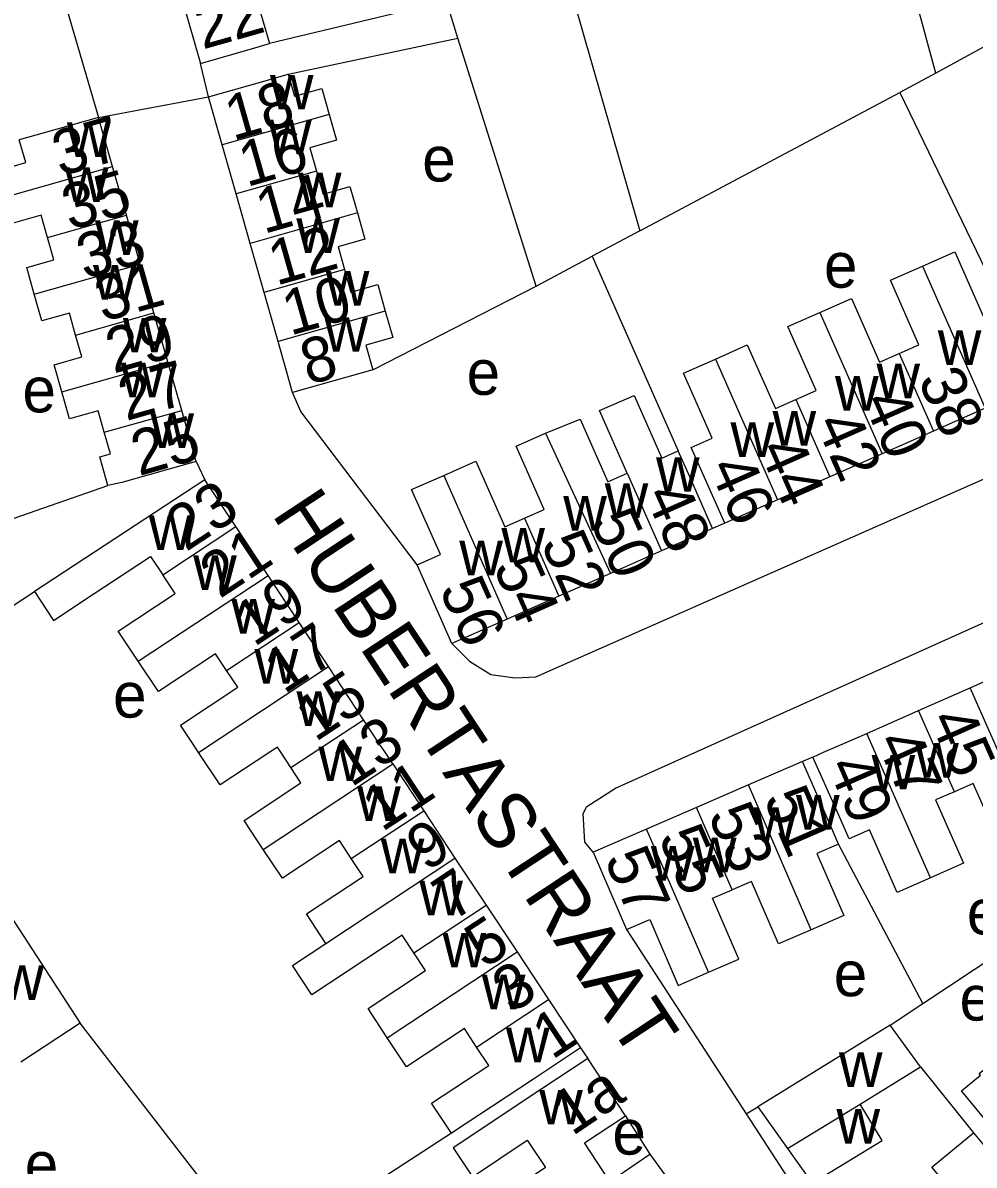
# Model space of a CAD drawing. Extents: x 159261 to 160849, y 382514 to 384534.
# Drawn here: x 160270.2 to 160354.6, y 383463.4 to 383564.7 of the extents above; entities that cross this region are included whole.
import ezdxf

# ---------------------------------------------------------------- set-up
doc = ezdxf.new("R2010")
doc.units = 0
for name, color, linetype in [('BLT_Basislijn', 7, 'Continuous'), ('BLT_Bebouwing', 7, 'Continuous'), ('BLT_Centroide', 7, 'Continuous'), ('BLT_Huisnummer', 7, 'Continuous'), ('BLT_Huisnummer_ tussenligend', 7, 'Continuous'), ('BLT_Huisnummer_reeks', 7, 'Continuous'), ('BLT_Onderverdeling_panden', 7, 'Continuous'), ('BLT_Straatnaam', 7, 'Continuous'), ('BLT_Vlakafsluiter', 7, 'Continuous')]:
    doc.layers.add(name, color=color, linetype=linetype)

msp = doc.modelspace()

# ---------------------------------------------------------------- linework, layer by layer
at = {"layer": 'BLT_Basislijn'}
for p, q in [((160315.03, 383580.9), (160324.95, 383546.27)), ((160373.11, 383572.25), (160351.21, 383560.24)), ((160273.28, 383568.79), (160276.93, 383556.33)), ((160293.77, 383560.15), (160308.8, 383563.35)), ((160315.77, 383541.34), (160308.8, 383563.35)), ((160286.7, 383558.14), (160285.99, 383561.11)), ((160351.21, 383560.24), (160348.01, 383558.54)), ((160324.95, 383546.27), (160348.01, 383558.54)), ((160348.01, 383558.54), (160357.2, 383539.49)), ((160324.95, 383546.27), (160320.72, 383544.01)), ((160315.77, 383541.34), (160320.72, 383544.01)), ((160320.72, 383544.01), (160328.36, 383526.74)), ((160301.28, 383533.94), (160315.77, 383541.34)), ((160285.59, 383525.8), (160286.37, 383524.16)), ((160268.86, 383520.57), (160277.76, 383523.68)), ((160332.49, 383520.33), (160331.39, 383519.86)), ((160266.28, 383511.01), (160271.25, 383514.26)), ((160340.31, 383499.58), (160339.4, 383499.18)), ((160350.07, 383477.72), (160375.85, 383494.83)), ((160350.07, 383477.72), (160342.58, 383491.85)), ((160323.78, 383484.27), (160334.4, 383467.92)), ((160347.17, 383475.8), (160350.07, 383477.72)), ((160287.38, 383460.38), (160275.29, 383475.98)), ((160319.69, 383473.77), (160320.33, 383472.82)), ((160349.86, 383472.08), (160354.56, 383466.25)), ((160323.68, 383467.76), (160325.85, 383464.35)), ((160334.4, 383467.92), (160335.42, 383468.56)), ((160334.4, 383467.92), (160347.36, 383447.97)), ((160308.24, 383466.2), (160291.06, 383455.07)), ((160322.29, 383461.92), (160325.85, 383464.35)), ((160325.85, 383464.35), (160327.16, 383462.51))]:
    msp.add_line(p, q, dxfattribs=at)
for points in [[(160308.29, 383509.66), (160309.84, 383508.09), (160311.74, 383506.91), (160313.89, 383506.61), (160315.74, 383506.7), (160377.81, 383534.11), (160390.63, 383541.51), (160406.21, 383552.19), (160447.07, 383583.47), (160450.73, 383593.39)], [(160351.21, 383560.24), (160346.25, 383578.54), (160343.07, 383588.58)], [(160320.81, 383491.14), (160320.08, 383492.03), (160319.93, 383494.56), (160320.25, 383495.2), (160322.79, 383496.82), (160377.81, 383521.53), (160402.11, 383534.27), (160431.08, 383555.98), (160454.87, 383574.92), (160465.53, 383577.42)], [(160308.8, 383563.35), (160307.81, 383566.63), (160292.1, 383562.87)], [(160305.21, 383516.64), (160294.89, 383530.22), (160294.14, 383531.91)]]:
    msp.add_lwpolyline(points, dxfattribs=at)
at = {"layer": 'BLT_Bebouwing'}
for p, q in [((160289.44, 383572.14), (160292.1, 383562.87)), ((160283.32, 383570.38), (160285.99, 383561.11)), ((160287.9, 383553.9), (160286.7, 383558.14)), ((160278.17, 383551.96), (160276.93, 383556.33)), ((160289.14, 383549.54), (160287.9, 383553.9)), ((160279.4, 383547.64), (160278.17, 383551.96)), ((160290.39, 383545.15), (160289.14, 383549.54)), ((160280.63, 383543.3), (160279.4, 383547.64)), ((160291.62, 383540.8), (160290.39, 383545.15)), ((160281.85, 383538.99), (160280.63, 383543.3)), ((160292.86, 383536.45), (160291.62, 383540.8)), ((160283.08, 383534.64), (160281.85, 383538.99)), ((160294.14, 383531.91), (160292.86, 383536.45)), ((160284.31, 383530.33), (160283.08, 383534.64)), ((160355.6, 383530.52), (160351, 383528.49)), ((160285.59, 383525.8), (160284.31, 383530.33)), ((160351, 383528.49), (160346.45, 383526.48)), ((160346.45, 383526.48), (160341.81, 383524.44)), ((160341.81, 383524.44), (160337.17, 383522.39)), ((160286.37, 383524.16), (160271.25, 383514.26)), ((160289.11, 383520.02), (160286.37, 383524.16)), ((160337.17, 383522.39), (160332.49, 383520.33)), ((160291.97, 383515.69), (160289.11, 383520.02)), ((160331.39, 383519.86), (160326.88, 383517.86)), ((160326.88, 383517.86), (160322.34, 383515.86)), ((160308.29, 383509.66), (160305.21, 383516.64)), ((160294.74, 383511.51), (160291.97, 383515.69)), ((160322.34, 383515.86), (160317.77, 383513.85)), ((160317.77, 383513.85), (160313.18, 383511.82)), ((160297.32, 383507.6), (160294.74, 383511.51)), ((160313.18, 383511.82), (160308.29, 383509.66)), ((160300.44, 383502.89), (160297.32, 383507.6)), ((160354.25, 383505.73), (160358.91, 383507.78)), ((160349.68, 383503.71), (160354.25, 383505.73)), ((160345.08, 383501.68), (160349.68, 383503.71)), ((160339.4, 383499.18), (160334.59, 383497.1)), ((160303.03, 383498.97), (160305.78, 383494.82)), ((160334.59, 383497.1), (160329.98, 383495.1)), ((160329.98, 383495.1), (160325.56, 383493.19)), ((160305.78, 383494.82), (160308.55, 383490.61)), ((160325.56, 383493.19), (160320.81, 383491.14)), ((160320.81, 383491.14), (160323.78, 383484.27)), ((160308.55, 383490.61), (160311.32, 383486.43)), ((160311.32, 383486.43), (160314.06, 383482.29)), ((160269.1, 383485.53), (160275.29, 383475.98)), ((160314.06, 383482.29), (160316.85, 383478.07)), ((160316.85, 383478.07), (160319.69, 383473.77)), ((160275.29, 383475.98), (160270.03, 383472.52)), ((160347.17, 383475.8), (160335.42, 383468.56)), ((160349.86, 383472.08), (160347.17, 383475.8)), ((160323.68, 383467.76), (160320.33, 383472.82))]:
    msp.add_line(p, q, dxfattribs=at)
for points in [[(160285.99, 383561.11), (160290.8, 383562.49), (160292.1, 383562.87)], [(160286.7, 383558.14), (160291.51, 383559.51), (160293.77, 383560.15)], [(160293.77, 383560.15), (160294.32, 383558.21), (160296.73, 383558.89), (160297.39, 383556.59)], [(160276.93, 383556.33), (160272.12, 383554.97), (160269.9, 383554.34)], [(160297.39, 383556.59), (160298.04, 383554.3), (160295.68, 383553.62), (160296.26, 383551.56)], [(160268.7, 383549.28), (160268.03, 383551.62), (160270.47, 383552.31), (160269.9, 383554.34)], [(160296.26, 383551.56), (160296.85, 383549.51), (160299.24, 383550.19), (160299.91, 383547.85)], [(160272.41, 383545.66), (160271.85, 383547.64), (160269.36, 383546.93), (160268.7, 383549.28)], [(160299.91, 383547.85), (160300.57, 383545.51), (160298.2, 383544.84), (160298.76, 383542.83)], [(160271.23, 383540.64), (160270.56, 383543), (160272.97, 383543.68), (160272.41, 383545.66)], [(160350.04, 383543.14), (160352.9, 383544.4), (160355.41, 383538.7), (160357.2, 383539.49)], [(160298.76, 383542.83), (160299.33, 383540.82), (160301.71, 383541.5), (160302.37, 383539.15)], [(160347.97, 383535.37), (160349.71, 383536.14), (160347.18, 383541.88), (160350.04, 383543.14)], [(160274.9, 383537.02), (160274.35, 383538.97), (160271.9, 383538.27), (160271.23, 383540.64)], [(160340.91, 383539.02), (160343.73, 383540.27), (160346.23, 383534.6), (160347.97, 383535.37)], [(160302.37, 383539.15), (160303.04, 383536.81), (160300.65, 383536.13), (160301.28, 383533.94)], [(160338.79, 383531.29), (160340.61, 383532.09), (160338.1, 383537.78), (160340.91, 383539.02)], [(160273.69, 383531.98), (160273.01, 383534.37), (160275.45, 383535.07), (160274.9, 383537.02)], [(160331.66, 383534.89), (160334.49, 383536.14), (160336.98, 383530.49), (160338.79, 383531.29)], [(160332.49, 383520.33), (160330.47, 383524.9), (160329.52, 383527.05), (160331.38, 383527.87), (160328.83, 383533.64), (160331.66, 383534.89)], [(160301.28, 383533.94), (160298.95, 383533.28), (160294.14, 383531.91)], [(160277.44, 383528.39), (160276.9, 383530.3), (160274.37, 383529.58), (160273.69, 383531.98)], [(160323.84, 383524.76), (160321.39, 383530.31), (160324.44, 383531.66), (160326.9, 383526.09), (160328.36, 383526.74)], [(160316.6, 383528.31), (160319.66, 383529.56), (160322.12, 383524), (160323.84, 383524.76)], [(160277.76, 383523.68), (160277.04, 383526.2), (160277.99, 383526.47), (160277.44, 383528.39)], [(160314.72, 383520.77), (160316.46, 383521.54), (160313.99, 383527.16), (160316.6, 383528.31)], [(160331.39, 383519.86), (160329.38, 383524.43), (160328.36, 383526.74)], [(160285.59, 383525.8), (160279.01, 383523.93), (160277.76, 383523.68)], [(160307.56, 383524.56), (160310.4, 383525.82), (160312.97, 383520), (160314.72, 383520.77)], [(160305.21, 383516.64), (160307.26, 383517.54), (160304.71, 383523.31), (160307.56, 383524.56)], [(160271.25, 383514.26), (160272.95, 383511.69), (160276.47, 383514.02), (160281.54, 383517.38), (160282.63, 383515.73)], [(160280.46, 383508.07), (160278.68, 383510.75), (160283.72, 383514.09), (160282.63, 383515.73)], [(160288.3, 383507.25), (160287.32, 383508.74), (160282.24, 383505.38), (160280.46, 383508.07)], [(160285.81, 383499.99), (160285.32, 383500.73), (160284.21, 383502.4), (160289.28, 383505.77), (160288.3, 383507.25)], [(160303.03, 383498.97), (160302.35, 383500), (160301.87, 383500.73), (160300.44, 383502.89)], [(160340.31, 383499.58), (160341.26, 383500), (160342.9, 383500.73), (160345.08, 383501.68)], [(160294, 383498.64), (160293.1, 383500), (160292.8, 383500.45), (160292.12, 383500), (160287.72, 383497.1), (160285.81, 383499.99)], [(160342.58, 383491.85), (160341.39, 383494.6), (160339.4, 383499.18)], [(160350.73, 383488.86), (160347.79, 383487.57), (160345.34, 383493.11), (160343.52, 383492.31), (160342.33, 383495.01), (160340.31, 383499.58)], [(160291.55, 383491.39), (160289.85, 383493.96), (160294.89, 383497.29), (160294, 383498.64)], [(160359.87, 383492.97), (160356.97, 383491.69), (160354.52, 383497.24), (160352.86, 383496.5)], [(160352.86, 383496.5), (160351.19, 383495.77), (160353.67, 383490.16), (160350.73, 383488.86)], [(160299.35, 383490.57), (160298.31, 383492.16), (160293.25, 383488.82), (160291.55, 383491.39)], [(160342.58, 383491.85), (160340.66, 383491.02), (160343.04, 383485.52), (160340.15, 383484.26)], [(160297.1, 383483.04), (160295.37, 383485.66), (160300.4, 383488.99), (160299.35, 383490.57)], [(160340.15, 383484.26), (160337.26, 383483.01), (160334.87, 383488.54), (160333.14, 383487.79)], [(160331.06, 383480.49), (160333.75, 383481.66), (160331.41, 383487.05), (160333.14, 383487.79)], [(160323.78, 383484.27), (160325.84, 383485.16), (160328.36, 383479.32), (160331.06, 383480.49)], [(160304.91, 383482.2), (160303.88, 383483.77), (160295.87, 383478.47), (160294.14, 383481.09), (160297.1, 383483.04)], [(160302.55, 383474.68), (160300.85, 383477.27), (160305.95, 383480.64), (160304.91, 383482.2)], [(160310.47, 383473.85), (160309.39, 383475.49), (160304.26, 383472.1), (160302.55, 383474.68)], [(160308.24, 383466.2), (160306.48, 383468.86), (160311.55, 383472.22), (160310.47, 383473.85)], [(160319.69, 383473.77), (160315.52, 383471.01), (160308.24, 383466.2)], [(160320.33, 383472.82), (160316.16, 383470.07), (160308.39, 383464.92), (160310.11, 383462.34), (160314.97, 383465.59), (160316.6, 383463.17), (160314.39, 383461.69), (160316.73, 383458.2)], [(160357.51, 383465.1), (160353.49, 383469.97), (160355.17, 383471.35), (160355.05, 383471.5), (160357.26, 383473.32)], [(160344.49, 383468.79), (160349.86, 383472.08)], [(160338.07, 383464.84), (160340.24, 383461.78), (160346.44, 383465.55), (160344.49, 383468.79)], [(160322.29, 383461.92), (160320.06, 383465.35), (160323.68, 383467.76)], [(160335.42, 383468.56), (160338.07, 383464.84)], [(160353.57, 383452.09), (160350.59, 383455.72), (160354.44, 383458.89), (160350.87, 383463.2), (160354.56, 383466.25)], [(160354.56, 383466.25), (160356.32, 383464.11), (160357.51, 383465.1)]]:
    msp.add_lwpolyline(points, dxfattribs=at)
at = {"layer": 'BLT_Onderverdeling_panden'}
for p, q in [((160297.39, 383556.59), (160287.9, 383553.9)), ((160268.7, 383549.28), (160278.17, 383551.96)), ((160296.26, 383551.56), (160289.14, 383549.54)), ((160299.91, 383547.85), (160290.39, 383545.15)), ((160272.41, 383545.66), (160279.4, 383547.64)), ((160271.23, 383540.64), (160280.63, 383543.3)), ((160298.76, 383542.83), (160291.62, 383540.8)), ((160350.04, 383543.14), (160355.6, 383530.52)), ((160274.9, 383537.02), (160281.85, 383538.99)), ((160302.37, 383539.15), (160292.86, 383536.45)), ((160340.91, 383539.02), (160346.45, 383526.48)), ((160273.69, 383531.98), (160283.08, 383534.64)), ((160331.66, 383534.89), (160337.17, 383522.39)), ((160347.97, 383535.37), (160351, 383528.49)), ((160338.79, 383531.29), (160341.81, 383524.44)), ((160277.44, 383528.39), (160284.31, 383530.33)), ((160316.6, 383528.31), (160322.34, 383515.86)), ((160307.56, 383524.56), (160313.18, 383511.82)), ((160323.84, 383524.76), (160326.88, 383517.86)), ((160314.72, 383520.77), (160317.77, 383513.85)), ((160282.63, 383515.73), (160289.11, 383520.02)), ((160280.46, 383508.07), (160291.97, 383515.69)), ((160288.3, 383507.25), (160294.74, 383511.51)), ((160285.81, 383499.99), (160297.32, 383507.6)), ((160359.87, 383492.97), (160354.25, 383505.73)), ((160352.86, 383496.5), (160349.68, 383503.71)), ((160294, 383498.64), (160300.44, 383502.89)), ((160350.73, 383488.86), (160345.08, 383501.68)), ((160291.55, 383491.39), (160303.03, 383498.97)), ((160340.15, 383484.26), (160334.59, 383497.1)), ((160333.14, 383487.79), (160329.98, 383495.1)), ((160299.35, 383490.57), (160305.78, 383494.82)), ((160331.06, 383480.49), (160325.56, 383493.19)), ((160297.1, 383483.04), (160308.55, 383490.61)), ((160304.91, 383482.2), (160311.32, 383486.43)), ((160302.55, 383474.68), (160314.06, 383482.29)), ((160310.47, 383473.85), (160316.85, 383478.07)), ((160338.07, 383464.84), (160344.49, 383468.79))]:
    msp.add_line(p, q, dxfattribs=at)
at = {"layer": 'BLT_Vlakafsluiter'}
msp.add_line((160276.93, 383556.33), (160286.7, 383558.14), dxfattribs=at)

# ---------------------------------------------------------------- texts
at = {"layer": 'BLT_Centroide'}
for s, p in [('w', (160292.14, 383557.03)), ('w', (160274.13, 383552.81)), ('w', (160291.98, 383553.06)), ('e', (160305.65, 383550.64)), ('w', (160273.95, 383548.81)), ('w', (160294.62, 383548.34)), ('w', (160276.62, 383544.12)), ('w', (160294.48, 383544.31)), ('e', (160341.29, 383541.22)), ('w', (160276.45, 383540.16)), ('w', (160297.09, 383539.62)), ('w', (160296.97, 383535.53)), ('w', (160279.09, 383535.47)), ('w', (160351.39, 383534.36)), ('w', (160278.9, 383531.5)), ('e', (160309.59, 383531.71)), ('w', (160345.95, 383531.41)), ('e', (160270.18, 383530.16)), ('w', (160342.27, 383530.3)), ('w', (160281.54, 383527)), ('w', (160336.73, 383527.2)), ('w', (160333, 383526.2)), ('w', (160326.39, 383523.11)), ('w', (160321.84, 383520.8)), ('w', (160318.16, 383519.67)), ('w', (160281.39, 383517.94)), ('w', (160312.67, 383516.84)), ('w', (160308.94, 383515.69)), ('w', (160285.33, 383514.41)), ('w', (160288.72, 383510.53)), ('w', (160290.77, 383506.08)), ('e', (160278.22, 383503.08)), ('w', (160294.49, 383502.34)), ('w', (160296.44, 383497.44)), ('w', (160349.38, 383497.75)), ('w', (160345.52, 383496.7)), ('w', (160299.87, 383493.91)), ('w', (160338.81, 383493.14)), ('w', (160335.06, 383492.05)), ('w', (160301.97, 383489.27)), ('w', (160329.66, 383489.34)), ('w', (160325.94, 383488.62)), ('w', (160305.39, 383485.53)), ('e', (160353.97, 383483.84)), ('w', (160307.45, 383480.91)), ('w', (160268.23, 383478.03)), ('e', (160342.16, 383478.36)), ('w', (160310.94, 383477.19)), ('e', (160353.32, 383476.2)), ('w', (160313.08, 383472.5)), ('w', (160342.62, 383470.31)), ('w', (160316.03, 383466.98)), ('w', (160342.4, 383465.28)), ('e', (160322.52, 383464.31)), ('e', (160270.39, 383461.45))]:
    msp.add_text(s, height=4, dxfattribs=at).set_placement(p)
at = {"layer": 'BLT_Huisnummer'}
for s, rotation, p in [('18', 15.8444, (160288.85, 383554.24)), ('37', 15.824, (160273.53, 383551.08)), ('33', 15.8289, (160275.69, 383541.92)), ('12', 15.8331, (160292.7, 383541.38)), ('29', 15.8362, (160278.26, 383533.58)), ('8', 15.84, (160295.54, 383532.56)), ('38', 293.8025, (160349.58, 383533.07)), ('25', 15.8338, (160280.51, 383524.49)), ('42', 293.8117, (160340.49, 383529.18)), ('46', 293.8117, (160331.03, 383525.28)), ('23', 33.5128, (160284.69, 383517.74)), ('50', 293.808, (160320.51, 383520.53)), ('56', 293.8076, (160307.12, 383514.48)), ('17', 33.4587, (160293.39, 383505.09)), ('45', 293.7942, (160350.59, 383502.91)), ('13', 33.4569, (160299.35, 383496.84)), ('49', 293.4094, (160341.55, 383498.77)), ('53', 293.3979, (160330.96, 383494.44)), ('9', 33.4667, (160306.01, 383489.35)), ('57', 293.4067, (160321.76, 383490.54)), ('5', 33.4562, (160311.19, 383480.76)), ('1', 33.4612, (160317.17, 383472.67)), ('1a', 33.7826, (160318.95, 383465.9))]:
    msp.add_text(s, height=4, rotation=rotation, dxfattribs=at).set_placement(p)
at = {"layer": 'BLT_Huisnummer_ tussenligend'}
for s, rotation, p in [('16', 15.8331, (160290.07, 383550.13)), ('35', 15.8289, (160274.38, 383546.3)), ('14', 15.8331, (160291.59, 383545.97)), ('31', 15.8362, (160277.31, 383538.16)), ('10', 15.84, (160293.93, 383536.95)), ('27', 15.8338, (160279.38, 383529.38)), ('40', 293.8025, (160344.7, 383531.13)), ('44', 293.8117, (160335.44, 383526.91)), ('48', 293.8117, (160325.35, 383522.83)), ('21', 33.4587, (160287.68, 383513.57)), ('52', 293.808, (160316.13, 383518.56)), ('54', 293.808, (160311.9, 383516.46)), ('19', 33.4587, (160290.72, 383509.29)), ('15', 33.4569, (160296.16, 383500.86)), ('47', 293.7942, (160345.87, 383500.97)), ('11', 33.4667, (160302.08, 383492.87)), ('51', 293.4094, (160335.88, 383495.91)), ('55', 293.3979, (160326.56, 383492.48)), ('7', 33.4562, (160308.33, 383484.94)), ('3', 33.4612, (160313.62, 383476.78))]:
    msp.add_text(s, height=4, rotation=rotation, dxfattribs=at).set_placement(p)
at = {"layer": 'BLT_Huisnummer_reeks'}
msp.add_text('22', height=4, rotation=15.8444, dxfattribs=at).set_placement((160286.17, 383562.34))
at = {"layer": 'BLT_Straatnaam'}
for s, rotation, p in [('HUBERTASTRAAT', 303.4631, (160292.23, 383521.13)), ('DRAAIBOOMSTRAAT', 304.5268, (160241.38, 383463.73))]:
    msp.add_text(s, height=5, rotation=rotation, dxfattribs=at).set_placement(p)

doc.saveas('drawing.dxf')
